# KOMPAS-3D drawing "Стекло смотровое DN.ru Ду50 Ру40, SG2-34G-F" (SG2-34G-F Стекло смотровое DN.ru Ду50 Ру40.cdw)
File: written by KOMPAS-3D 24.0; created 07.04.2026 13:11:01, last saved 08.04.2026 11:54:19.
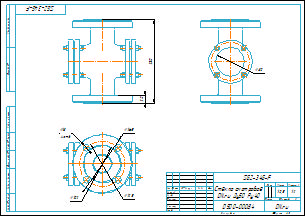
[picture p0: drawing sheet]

Document properties: Автор: Main; Форматы листов документа: A4; Полное имя файла: SG2-34G-FСтекло смотровое DN.ru Ду50 Ру40 (3d).cdw; Масса: 10.5; Наименование: Стекло смотровое DN.ru Ду50 Ру40; Количество листов документа: 1; Примечание: D500-00084

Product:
- Body: Тело 1  | qty 1
    Масса: 11.518228
- Part/product: Стекло смотровое DN.ru Ду50 Ру40  | designation SG2-34G-F
    Масса: 10.5
    Раздел спецификации: Прочие изделия
    Форматы листов документа: A4
    Примечание: D500-00084

Views: Вид 1, Снизу, Проекционный вид 2
Referenced files in D:\DN.ru Аутсерс\Стекло смотровое DN.ru\Стекло смотровое DN.ru SG2-34G-F тип В ГОСТ 21836-2021 Ду100 Ру16, углеродистая сталь, фланцевое\: SG2-34G-F тип В Стекло смотровое DN.ru Ду100 Ру16.m3d, SG2-34G-F тип ВСтекло смотровое DN.ru Ду100 Ру16.cdw
Referenced files in D:\DN.ru Аутсерс\Стекло смотровое DN.ru\SG2-34G-F Стекло смотровое DN.ru Ду50 Ру40\: SG2-34G-F Стекло смотровое DN.ru Ду50 Ру40.m3d
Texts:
  SG2-34G-F
  Стекло смотровое
  DN.ru Ду50 Ру40
  Стекло смотровое DN.ru Ду50 Ру40
  SG2-34G-F Стекло смотровое DN.ru Ду50 Ру40
Dimensions and other numbers on the sheet: 0; 3; 2; 4; 230; 20; 18; 4 отв.; 165; 102; 125; 1:2; 1; 10,5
